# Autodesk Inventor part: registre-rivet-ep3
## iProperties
Author: chr
Created: 2001-06
Part Number: registre-rivet-ep3
Material: Par défaut
Document SubType Name: Modélisation
Designer: chr
Control State: 0
Master: False
Checked Out: False
PropertySet Name: Design Tracking Control
Shininess: 20.0
PropertySet Name: _Private Model Information
Length Units: 11269
Angle Units: 11286
Time Units: 11279
Mass Units: 11290
Length Display Precision: 3
Angle Display Precision: 2
Compacted: False
Density: 0.0
Volumn: 0.0
Area: 0.0
PropertySet Name: Model Information
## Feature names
1. Révolution1 [Revolution]
2. Symétrie1 [Mirror]
